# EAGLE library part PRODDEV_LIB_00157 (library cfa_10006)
SN74CB3T3125, IC 3.3V QUAD FET SWITCH 14TSSOP
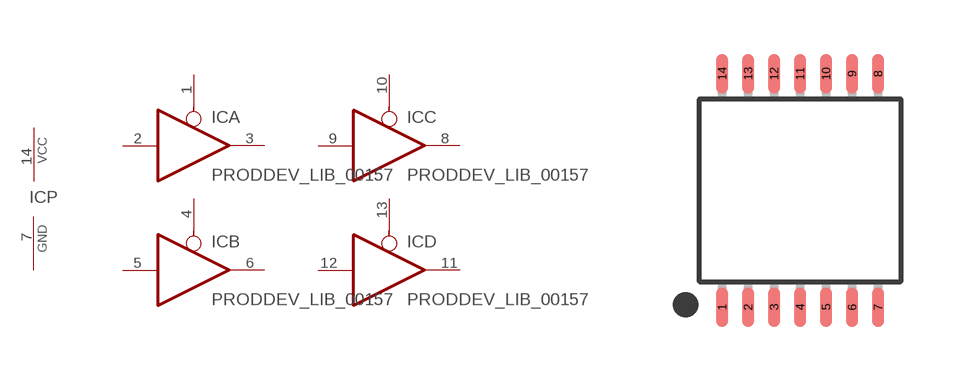
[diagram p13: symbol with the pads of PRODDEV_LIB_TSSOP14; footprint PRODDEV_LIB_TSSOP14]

Designator prefix IC; gates A=PRODDEV_LIB_74125-1 B=PRODDEV_LIB_74125-1 C=PRODDEV_LIB_74125-1 D=PRODDEV_LIB_74125-1 P=PRODDEV_LIB_PWRN

## PRODDEV_LIB_00157  [PRODDEV_LIB_TSSOP14]
1  A:OE  in
2  A:I  in
3  A:O  hiz
4  B:OE  in
5  B:I  in
6  B:O  hiz
7  P:GND  pwr
8  C:O  hiz
9  C:I  in
10  C:OE  in
11  D:O  hiz
12  D:I  in
13  D:OE  in
14  P:VCC  pwr

## Footprint PRODDEV_LIB_TSSOP14 (pad centres in mm)
smd 0.305 x 0.991: 1 -1.95,-2.918; 2 -1.3,-2.918; 3 -0.65,-2.918; 4 0,-2.918; 5 0.65,-2.918; 6 1.3,-2.918; 7 1.95,-2.918; 8 1.95,2.918; 9 1.3,2.918; 10 0.65,2.918; 11 0,2.918; 12 -0.65,2.918; 13 -1.3,2.918; 14 -1.95,2.918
